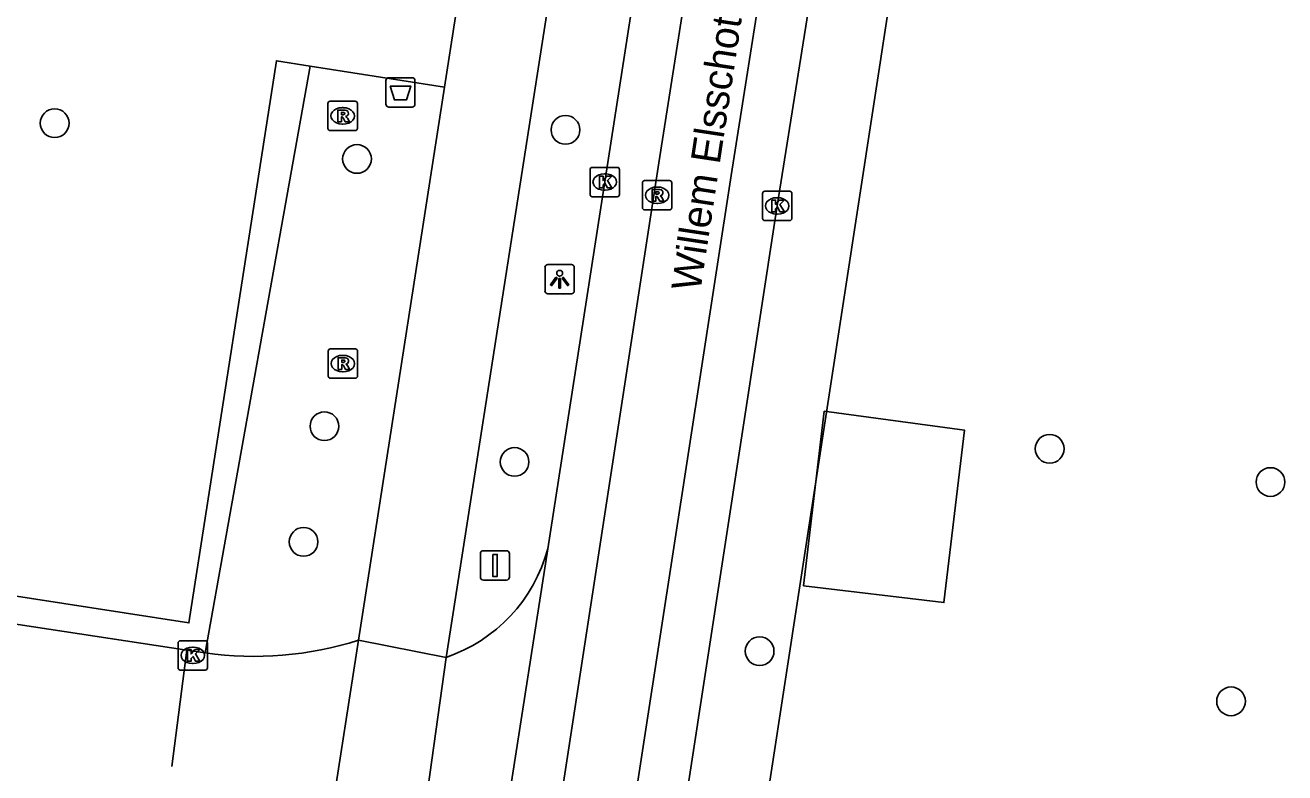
# Model space of a CAD drawing. Extents: x 161094 to 161705, y 379509 to 380907.
# Drawn here: x 161367.35 to 161410.24, y 380776.73 to 380802.2 of the extents above; entities that cross this region are included whole.
import ezdxf

# ---------------------------------------------------------------- set-up
doc = ezdxf.new("R2010")
doc.units = 0
for name, color, linetype in [('IMGEO_Afsluitpaal', 7, 'Continuous'), ('IMGEO_Afvalbak', 7, 'Continuous'), ('IMGEO_Boom', 7, 'Continuous'), ('IMGEO_Fietspad_gesloten', 7, 'Continuous'), ('IMGEO_Groenvoorziening', 7, 'Continuous'), ('IMGEO_Haag', 7, 'Continuous'), ('IMGEO_Hek', 7, 'Continuous'), ('IMGEO_Kolk', 7, 'Continuous'), ('IMGEO_Lichtpunt', 7, 'Continuous'), ('IMGEO_Openbare_ruimte_label', 7, 'Continuous'), ('IMGEO_Pand_vergunning_verleend', 7, 'Continuous'), ('IMGEO_Parkeervlak_open', 7, 'Continuous'), ('IMGEO_Rijbaan_lokaal_gesloten', 7, 'Continuous'), ('IMGEO_Rijbaan_lokaal_open', 7, 'Continuous'), ('IMGEO_Rioolput', 7, 'Continuous')]:
    doc.layers.add(name, color=color, linetype=linetype)

msp = doc.modelspace()

# ---------------------------------------------------------------- linework, layer by layer
at = {"layer": 'IMGEO_Afsluitpaal'}
for p, q in [((161382.852, 380783.4), (161382.852, 380784.2)), ((161382.852, 380784.2), (161382.852, 380783.4)), ((161382.952, 380784.3), (161383.742, 380784.3)), ((161383.742, 380784.3), (161382.952, 380784.3)), ((161383.842, 380784.2), (161383.842, 380783.4)), ((161383.842, 380783.4), (161383.842, 380784.2)), ((161383.742, 380783.3), (161382.952, 380783.3)), ((161382.952, 380783.3), (161383.742, 380783.3))]:
    msp.add_line(p, q, dxfattribs=at)
msp.add_lwpolyline([(161383.272, 380784.175), (161383.422, 380784.175), (161383.422, 380783.425), (161383.272, 380783.425), (161383.272, 380784.175)], dxfattribs=at)
for centre, start, end in [((161382.952, 380784.2), 90, 180), ((161382.952, 380784.2), 90, 180), ((161383.742, 380784.2), 0, 90), ((161383.742, 380784.2), 360, 90), ((161382.952, 380783.4), 180, 270), ((161382.952, 380783.4), 180, 270), ((161383.742, 380783.4), 270, 0), ((161383.742, 380783.4), 270, 0)]:
    msp.add_arc(centre, 0.1, start, end, dxfattribs=at)
at = {"layer": 'IMGEO_Afvalbak'}
for p, q in [((161379.734, 380800.409), (161380.524, 380800.409)), ((161380.524, 380800.409), (161379.734, 380800.409)), ((161379.634, 380799.509), (161379.634, 380800.309)), ((161379.634, 380800.309), (161379.634, 380799.509)), ((161380.624, 380800.309), (161380.624, 380799.509)), ((161380.624, 380799.509), (161380.624, 380800.309)), ((161380.524, 380799.409), (161379.734, 380799.409)), ((161379.734, 380799.409), (161380.524, 380799.409))]:
    msp.add_line(p, q, dxfattribs=at)
msp.add_lwpolyline([(161379.777, 380800.123), (161380.481, 380800.123), (161380.332, 380799.653), (161379.926, 380799.653), (161379.777, 380800.123)], dxfattribs=at)
for centre, start, end in [((161379.734, 380800.309), 90, 180), ((161379.734, 380800.309), 90, 180), ((161380.524, 380800.309), 0, 90), ((161380.524, 380800.309), 360, 90), ((161379.734, 380799.509), 180, 270), ((161379.734, 380799.509), 180, 270), ((161380.524, 380799.509), 270, 0), ((161380.524, 380799.509), 270, 0)]:
    msp.add_arc(centre, 0.1, start, end, dxfattribs=at)
at = {"layer": 'IMGEO_Boom'}
for centre in [(161368.355, 380798.858), (161385.748, 380798.632), (161378.65, 380797.641), (161377.54, 380788.538), (161402.235, 380787.77), (161384.015, 380787.323), (161409.753, 380786.637), (161376.83, 380784.6), (161392.359, 380780.876), (161408.412, 380779.169)]:
    msp.add_circle(centre, 0.489, dxfattribs=at)
at = {"layer": 'IMGEO_Fietspad_gesloten'}
for points in [[(161387.986, 380820.981), (161381.68, 380780.664)], [(161382.005, 380802.496), (161381.631, 380800.089)], [(161378.704, 380781.247), (161381.631, 380800.089)], [(161381.68, 380780.664), (161378.704, 380781.247)]]:
    msp.add_lwpolyline(points, dxfattribs=at)
at = {"layer": 'IMGEO_Groenvoorziening'}
msp.add_lwpolyline([(161405.29, 380858.44), (161376.121, 380668.459), (161366.925, 380608.735), (161353.592, 380520.726), (161347.606, 380481.216)], dxfattribs=at)
at = {"layer": 'IMGEO_Haag'}
msp.add_lwpolyline([(161377.051, 380800.8), (161373.475, 380780.822)], dxfattribs=at)
at = {"layer": 'IMGEO_Hek'}
for points in [[(161376.121, 380668.459), (161405.29, 380858.44)], [(161372.346, 380776.949), (161372.852, 380780.917)]]:
    msp.add_lwpolyline(points, dxfattribs=at)
at = {"layer": 'IMGEO_Kolk'}
for p, q in [((161386.66, 380797.355), (161387.512, 380797.355)), ((161386.585, 380796.429), (161386.585, 380797.281)), ((161387.073, 380797.135), (161387.098, 380797.135)), ((161387.586, 380797.281), (161387.586, 380796.429)), ((161387.096, 380796.575), (161387.071, 380796.575)), ((161392.531, 380796.542), (161393.383, 380796.542)), ((161387.512, 380796.355), (161386.66, 380796.355)), ((161392.456, 380795.616), (161392.456, 380796.468)), ((161392.944, 380796.322), (161392.969, 380796.322)), ((161393.457, 380796.468), (161393.457, 380795.616)), ((161392.967, 380795.762), (161392.942, 380795.762)), ((161393.383, 380795.542), (161392.531, 380795.542)), ((161372.557, 380780.308), (161372.557, 380781.16)), ((161372.632, 380781.234), (161373.484, 380781.234)), ((161373.558, 380781.16), (161373.558, 380780.308)), ((161373.045, 380781.014), (161373.07, 380781.014)), ((161373.484, 380780.234), (161372.632, 380780.234)), ((161373.068, 380780.454), (161373.043, 380780.454))]:
    msp.add_line(p, q, dxfattribs=at)
for points in [[(161386.66, 380797.355), (161387.512, 380797.355)], [(161386.585, 380796.429), (161386.585, 380797.281)], [(161386.906, 380797.055), (161387.029, 380797.055), (161387.029, 380796.904), (161387.159, 380797.055), (161387.323, 380797.055), (161387.177, 380796.904), (161387.33, 380796.655), (161387.178, 380796.655), (161387.093, 380796.819), (161387.029, 380796.752), (161387.029, 380796.655), (161386.906, 380796.655), (161386.906, 380797.055)], [(161387.586, 380797.281), (161387.586, 380796.429)], [(161392.531, 380796.542), (161393.383, 380796.542)], [(161387.512, 380796.355), (161386.66, 380796.355)], [(161392.456, 380795.616), (161392.456, 380796.468)], [(161392.777, 380796.242), (161392.9, 380796.242), (161392.9, 380796.091), (161393.03, 380796.242), (161393.194, 380796.242), (161393.048, 380796.091), (161393.201, 380795.842), (161393.049, 380795.842), (161392.964, 380796.006), (161392.9, 380795.939), (161392.9, 380795.842), (161392.777, 380795.842), (161392.777, 380796.242)], [(161393.457, 380796.468), (161393.457, 380795.616)], [(161393.383, 380795.542), (161392.531, 380795.542)], [(161372.557, 380780.308), (161372.557, 380781.16)], [(161372.632, 380781.234), (161373.484, 380781.234)], [(161373.558, 380781.16), (161373.558, 380780.308)], [(161372.878, 380780.934), (161373.001, 380780.934), (161373.001, 380780.783), (161373.131, 380780.934), (161373.295, 380780.934), (161373.149, 380780.783), (161373.302, 380780.534), (161373.15, 380780.534), (161373.065, 380780.698), (161373.001, 380780.631), (161373.001, 380780.534), (161372.878, 380780.534), (161372.878, 380780.934)], [(161373.484, 380780.234), (161372.632, 380780.234)]]:
    msp.add_lwpolyline(points, dxfattribs=at)
for centre, start, end in [((161386.662, 380797.279), 91.552, 178.448), ((161386.662, 380797.279), 91.552, 178.448), ((161387.51, 380797.279), 1.552, 88.448), ((161387.51, 380797.279), 1.552, 88.448), ((161392.533, 380796.466), 91.552, 178.448), ((161392.533, 380796.466), 91.552, 178.448), ((161393.381, 380796.466), 1.552, 88.448), ((161393.381, 380796.466), 1.552, 88.448), ((161386.662, 380796.431), 181.552, 268.448), ((161386.662, 380796.431), 181.552, 268.448), ((161387.51, 380796.431), 271.552, 358.448), ((161387.51, 380796.431), 271.552, 358.448), ((161392.533, 380795.618), 181.552, 268.448), ((161392.533, 380795.618), 181.552, 268.448), ((161393.381, 380795.618), 271.552, 358.448), ((161393.381, 380795.618), 271.552, 358.448), ((161372.634, 380781.158), 91.552, 178.448), ((161372.634, 380781.158), 91.552, 178.448), ((161373.482, 380781.158), 1.552, 88.448), ((161373.482, 380781.158), 1.552, 88.448), ((161372.634, 380780.31), 181.552, 268.448), ((161372.634, 380780.31), 181.552, 268.448), ((161373.482, 380780.31), 271.552, 358.448), ((161373.482, 380780.31), 271.552, 358.448)]:
    msp.add_arc(centre, 0.0765, start, end, dxfattribs=at)
for centre, major_axis, ratio, start_param, end_param in [((161387.072, 380796.855), (-0.387, 0.002), 0.722429, 4.712389, 7.853982), ((161387.097, 380796.855), (-0.39, 0.002), 0.717154, 1.570796, 4.712389), ((161392.943, 380796.042), (-0.387, 0.002), 0.722429, 4.712389, 7.853982), ((161392.968, 380796.042), (-0.39, 0.002), 0.717154, 1.570796, 4.712389), ((161373.044, 380780.734), (-0.387, 0.002), 0.722429, 4.712389, 7.853982), ((161373.069, 380780.734), (-0.39, 0.002), 0.717154, 1.570796, 4.712389)]:
    msp.add_ellipse(centre, major_axis=major_axis, ratio=ratio, start_param=start_param, end_param=end_param, dxfattribs=at)
at = {"layer": 'IMGEO_Lichtpunt'}
for p, q in [((161385.051, 380793.95), (161385.051, 380793.143)), ((161385.051, 380793.95), (161385.051, 380793.143)), ((161385.953, 380794.045), (161385.145, 380794.045)), ((161385.953, 380794.045), (161385.145, 380794.045)), ((161386.047, 380793.143), (161386.047, 380793.95)), ((161386.047, 380793.143), (161386.047, 380793.95)), ((161385.145, 380793.049), (161385.953, 380793.049)), ((161385.145, 380793.049), (161385.953, 380793.049))]:
    msp.add_line(p, q, dxfattribs=at)
for points in [[(161385.425, 380793.614), (161385.464, 380793.586), (161385.276, 380793.324), (161385.238, 380793.351), (161385.425, 380793.614)], [(161385.527, 380793.566), (161385.574, 380793.566), (161385.574, 380793.244), (161385.527, 380793.244), (161385.527, 380793.566)], [(161385.637, 380793.586), (161385.675, 380793.613), (161385.862, 380793.351), (161385.823, 380793.323), (161385.637, 380793.586)]]:
    msp.add_lwpolyline(points, dxfattribs=at)
msp.add_circle((161385.55, 380793.748), 0.0994, dxfattribs=at)
for centre, start, end in [((161385.145, 380793.95), 90, 180), ((161385.145, 380793.95), 90, 180), ((161385.953, 380793.95), 0, 90), ((161385.953, 380793.95), 0, 90), ((161385.145, 380793.143), 180, 270), ((161385.145, 380793.143), 180, 270), ((161385.953, 380793.143), 270, 0), ((161385.953, 380793.143), 270, 360)]:
    msp.add_arc(centre, 0.0946, start, end, dxfattribs=at)
at = {"layer": 'IMGEO_Pand_vergunning_verleend'}
msp.add_lwpolyline([(161393.85, 380783.106), (161394.561, 380789.046), (161399.337, 380788.4), (161398.634, 380782.533), (161393.85, 380783.106)], dxfattribs=at)
at = {"layer": 'IMGEO_Parkeervlak_open'}
for points in [[(161377.051, 380800.8), (161375.904, 380800.985), (161372.927, 380781.841), (161358.898, 380784.016), (161359.205, 380785.989), (161356.853, 380786.37), (161356.537, 380784.399), (161346.136, 380785.954)], [(161381.631, 380800.089), (161377.051, 380800.8)]]:
    msp.add_lwpolyline(points, dxfattribs=at)
at = {"layer": 'IMGEO_Rijbaan_lokaal_gesloten'}
for points in [[(161339.984, 380477.773), (161375.194, 380708.235), (161388.922, 380797.51), (161396.234, 380843.996), (161396.663, 380846.991)], [(161399.153, 380846.596), (161398.722, 380843.492), (161391.386, 380797.079), (161377.702, 380708.239), (161342.463, 380477.394)], [(161400.962, 380846.207), (161400.622, 380844.851), (161395.87, 380814.342), (161392.957, 380796.042), (161379.164, 380706.261), (161373.065, 380666.559), (161354.682, 380545.949), (161344.875, 380482.113)], [(161385.145, 380784.362), (161390.03, 380815.808)], [(161382.973, 380770.386), (161385.145, 380784.362)]]:
    msp.add_lwpolyline(points, dxfattribs=at)
at = {"layer": 'IMGEO_Rijbaan_lokaal_open'}
for points in [[(161345.988, 380785.001), (161372.852, 380780.917), (161373.475, 380780.822)], [(161378.704, 380781.247), (161377.763, 380775.191)], [(161380.846, 380774.64), (161381.68, 380780.664)]]:
    msp.add_lwpolyline(points, dxfattribs=at)
for centre, radius, start, end in [((161379.946, 380785.761), 5.384, 288.7865, 344.9397), ((161375.158, 380792.494), 11.793, 261.7946, 287.4987)]:
    msp.add_arc(centre, radius, start, end, dxfattribs=at)
at = {"layer": 'IMGEO_Rioolput'}
for p, q in [((161377.66, 380798.682), (161377.66, 380799.534)), ((161377.735, 380799.608), (161378.587, 380799.608)), ((161378.661, 380799.534), (161378.661, 380798.682)), ((161378.148, 380799.388), (161378.173, 380799.388)), ((161378.171, 380798.828), (161378.146, 380798.828)), ((161378.587, 380798.608), (161377.735, 380798.608)), ((161388.368, 380795.979), (161388.368, 380796.831)), ((161388.443, 380796.905), (161389.295, 380796.905)), ((161388.856, 380796.685), (161388.881, 380796.685)), ((161389.369, 380796.831), (161389.369, 380795.979)), ((161388.879, 380796.125), (161388.854, 380796.125)), ((161389.295, 380795.905), (161388.443, 380795.905)), ((161377.667, 380790.246), (161377.667, 380791.098)), ((161377.742, 380791.172), (161378.594, 380791.172)), ((161378.155, 380790.952), (161378.18, 380790.952)), ((161378.668, 380791.098), (161378.668, 380790.246)), ((161378.594, 380790.172), (161377.742, 380790.172)), ((161378.178, 380790.392), (161378.153, 380790.392))]:
    msp.add_line(p, q, dxfattribs=at)
for points in [[(161377.66, 380798.682), (161377.66, 380799.534)], [(161377.735, 380799.608), (161378.587, 380799.608)], [(161378.661, 380799.534), (161378.661, 380798.682)], [(161378.249, 380799.306), (161377.997, 380799.308), (161377.997, 380798.908)], [(161377.997, 380798.908), (161378.121, 380798.908), (161378.121, 380799.07), (161378.132, 380799.07)], [(161378.175, 380799.227), (161378.121, 380799.227), (161378.121, 380799.146)], [(161378.121, 380799.146), (161378.173, 380799.146)], [(161378.179, 380799.041), (161378.25, 380798.908), (161378.39, 380798.908), (161378.325, 380799.034)], [(161378.587, 380798.608), (161377.735, 380798.608)], [(161388.368, 380795.979), (161388.368, 380796.831)], [(161388.443, 380796.905), (161389.295, 380796.905)], [(161388.957, 380796.603), (161388.705, 380796.605), (161388.705, 380796.205)], [(161388.883, 380796.524), (161388.829, 380796.524), (161388.829, 380796.443)], [(161389.369, 380796.831), (161389.369, 380795.979)], [(161388.705, 380796.205), (161388.829, 380796.205), (161388.829, 380796.367), (161388.84, 380796.367)], [(161388.829, 380796.443), (161388.881, 380796.443)], [(161388.887, 380796.338), (161388.958, 380796.205), (161389.098, 380796.205), (161389.033, 380796.331)], [(161389.295, 380795.905), (161388.443, 380795.905)], [(161377.667, 380790.246), (161377.667, 380791.098)], [(161377.742, 380791.172), (161378.594, 380791.172)], [(161378.668, 380791.098), (161378.668, 380790.246)], [(161378.256, 380790.87), (161378.004, 380790.872), (161378.004, 380790.472)], [(161378.004, 380790.472), (161378.128, 380790.472), (161378.128, 380790.634), (161378.139, 380790.634)], [(161378.182, 380790.791), (161378.128, 380790.791), (161378.128, 380790.71)], [(161378.128, 380790.71), (161378.18, 380790.71)], [(161378.186, 380790.605), (161378.257, 380790.472), (161378.397, 380790.472), (161378.332, 380790.598)], [(161378.594, 380790.172), (161377.742, 380790.172)]]:
    msp.add_lwpolyline(points, dxfattribs=at)
for centre, radius, start, end in [((161377.737, 380799.532), 0.0765, 91.552, 178.448), ((161377.737, 380799.532), 0.0765, 91.552, 178.448), ((161378.585, 380799.532), 0.0765, 1.552, 88.448), ((161378.585, 380799.532), 0.0765, 1.552, 88.448), ((161378.131, 380799.017), 0.0533, 26.0293, 88.6989), ((161378.157, 380799.335), 0.19, 274.7715, 282.9687), ((161378.181, 380799.131), 0.0964, 77.0061, 93.1865), ((161378.195, 380799.188), 0.0378, 276.6634, 79.6772), ((161378.248, 380799.196), 0.109, 350.3612, 89.416), ((161378.246, 380799.196), 0.112, 277.5842, 350.9817), ((161378.23, 380798.981), 0.108, 29.5134, 73.7905), ((161377.737, 380798.684), 0.0765, 181.552, 268.448), ((161377.737, 380798.684), 0.0765, 181.552, 268.448), ((161378.585, 380798.684), 0.0765, 271.552, 358.448), ((161378.585, 380798.684), 0.0765, 271.552, 358.448), ((161388.445, 380796.829), 0.0765, 91.552, 178.448), ((161388.445, 380796.829), 0.0765, 91.552, 178.448), ((161388.889, 380796.428), 0.0964, 77.0061, 93.1865), ((161388.903, 380796.485), 0.0378, 276.6634, 79.6772), ((161388.956, 380796.493), 0.109, 350.3612, 89.416), ((161389.293, 380796.829), 0.0765, 1.552, 88.448), ((161389.293, 380796.829), 0.0765, 1.552, 88.448), ((161388.839, 380796.314), 0.0533, 26.0293, 88.6989), ((161388.865, 380796.632), 0.19, 274.7715, 282.9687), ((161388.954, 380796.493), 0.112, 277.5842, 350.9817), ((161388.938, 380796.278), 0.108, 29.5134, 73.7905), ((161388.445, 380795.981), 0.0765, 181.552, 268.448), ((161388.445, 380795.981), 0.0765, 181.552, 268.448), ((161389.293, 380795.981), 0.0765, 271.552, 358.448), ((161389.293, 380795.981), 0.0765, 271.552, 358.448), ((161377.744, 380791.096), 0.0765, 91.552, 178.448), ((161377.744, 380791.096), 0.0765, 91.552, 178.448), ((161378.592, 380791.096), 0.0765, 1.552, 88.448), ((161378.592, 380791.096), 0.0765, 1.552, 88.448), ((161378.138, 380790.581), 0.0533, 26.0293, 88.6989), ((161378.164, 380790.899), 0.19, 274.7715, 282.9687), ((161378.188, 380790.695), 0.0964, 77.0061, 93.1865), ((161378.202, 380790.752), 0.0378, 276.6634, 79.6772), ((161378.255, 380790.76), 0.109, 350.3612, 89.416), ((161378.253, 380790.76), 0.112, 277.5842, 350.9817), ((161378.237, 380790.545), 0.108, 29.5134, 73.7905), ((161377.744, 380790.248), 0.0765, 181.552, 268.448), ((161377.744, 380790.248), 0.0765, 181.552, 268.448), ((161378.592, 380790.248), 0.0765, 271.552, 358.448), ((161378.592, 380790.248), 0.0765, 271.552, 358.448)]:
    msp.add_arc(centre, radius, start, end, dxfattribs=at)
for centre, major_axis, ratio, start_param, end_param in [((161378.147, 380799.108), (-0.387, 0.002), 0.722429, 4.712389, 7.853982), ((161378.172, 380799.108), (-0.39, 0.002), 0.717154, 1.570796, 4.712389), ((161388.855, 380796.405), (-0.387, 0.002), 0.722429, 4.712389, 7.853982), ((161388.88, 380796.405), (-0.39, 0.002), 0.717154, 1.570796, 4.712389), ((161378.154, 380790.672), (-0.387, 0.002), 0.722429, 4.712389, 7.853982), ((161378.179, 380790.672), (-0.39, 0.002), 0.717154, 1.570796, 4.712389)]:
    msp.add_ellipse(centre, major_axis=major_axis, ratio=ratio, start_param=start_param, end_param=end_param, dxfattribs=at)

# ---------------------------------------------------------------- texts
at = {"layer": 'IMGEO_Openbare_ruimte_label'}
msp.add_text('Willem Elsschotlaan', height=1, rotation=81.3758, dxfattribs=at).set_placement((161390.339, 380793.1))

doc.saveas('drawing.dxf')
